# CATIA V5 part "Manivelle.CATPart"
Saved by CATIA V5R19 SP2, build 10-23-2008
Part number: Manivelle
Bounding box of the stored display mesh (mm): x -60 to 131.111, y -14 to 14, z -40 to 14
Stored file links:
  D:\thinkmotion-MPB\Dropbox\CIAO82010_JCF\SAINT-AIME\0558-SaintAime\CAO2\CAO\Manivelle.CATPart
  D:\thinkmotion-MPB\Dropbox\CIAO82010_JCF\SAINT-AIME\0558-SaintAime\CAO2\CAO\Mecanisme_558.CATProduct
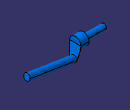
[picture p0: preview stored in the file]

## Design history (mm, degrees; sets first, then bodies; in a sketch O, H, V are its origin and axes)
Set1
  Plane1: type Offset, RefPlane xy-plane, Offset 20, reversed
  Plane2: type Offset, RefPlane Plane1, Offset 20, reversed
  Curve1: Elements (vertex [element of Sketch4 | element of Sketch4]; vertex [element of Sketch3 | element of Sketch3]; vertex [element of Sketch2 | element of Sketch2])
  Curve2: Elements (vertex [element of Sketch4 | element of Sketch4]; vertex [element of Sketch3 | element of Sketch3]; vertex [element of Sketch2 | element of Sketch2])
  Curve3: Elements (vertex [element of Sketch4 | element of Sketch4]; vertex [element of Sketch3 | element of Sketch3]; vertex [element of Sketch2 | element of Sketch2])
  Curve4: Elements (vertex [element of Sketch4 | element of Sketch4]; vertex [element of Sketch3 | element of Sketch3]; vertex [element of Sketch2 | element of Sketch2])
  Plane3: type Tangent, Support face of Pad1, RefPoint Sketch8.P1
  Point1: type OnSurface, Support end face of Pad3, Length 0, Direction (-0.6218, -0.213, 0.7536)
  Line1: type Normal, RefPoint Point1, RefSkin end face of Pad3, Start 0, End 20
  Line2: type Normal, RefPoint Sketch8.O, RefSkin xy-plane, Start 0, End 20
  Intersect1: ToIntersect1 Line2, ToIntersect2 Line1
  Point2: type OnPlane, Support end face of Pad1, H 0, V 0, Direction (0, 1, 0)
  Line3: type PtPt, FirstPoint Point2, SecondPoint Sketch8.P1
  Intersect2: ToIntersect1 Line3, ToIntersect2 Line1
Set2
  Point3: (10, 0, 0)
  Point4: (14.7998, 0, -31.2692)
  Line4: type PtPt, FirstPoint {point type Coord, X 10, Y 0, Z 0}, SecondPoint {point type Coord, X 14.7998, Y 0, Z -31.2692}
Set3
  Line5: type PtPt, FirstPoint {point type Coord, X 0, Y 0, Z -33.657}, SecondPoint {point type Coord, X 0, Y 43, Z 74.575}
  Line6: type Normal, RefPoint {point type Center, Curve edge [face of Pad2 from Sketch6.A1 | end face of Pad2]}, RefSkin end face of Pad2, Start 0, End 20
  Line7: type Normal, RefPoint {point type Center, Curve edge [end face of Pad3 | face of Pad3]}, RefSkin end face of Pad3, Start 0, End 20
  Intersect3: ToIntersect1 Line6, ToIntersect2 Line7
Body1 (main body)
  Sketch1 on yz-plane, origin (0, 0, 0), H (0, 1, 0), V (0, 0, 1)
    circle A1 centre (0, 0) radius 14
    radius A1 = 14
  Pad1: profile Sketch1, direction (1, 0, 0), length 10, mirrored extent
  Sketch2 on Plane2, origin (0, 0, -40), H (1, 0, 0), V (0, 1, 0)
    line L1 (16.14, 5) -> (16.14, -5)
    line L2 (16.14, -5) -> (12.0561, -3.8503)
    line L3 (16.14, 5) -> (12.0561, 3.8503)
    point P4 (12.0561, 3.8503)
    arc A1 centre (13.14, 0) radius 4 from (12.0561, 3.8503) to (12.0561, -3.8503) ccw
    point P5 (13.14, 0)
    point P6 (12.0561, 3.8503)
    reference projected line E1 (10, 14) -> (10, -14) from edge [face of Pad1 from Sketch1.A1 | end face of Pad1]
    length L1 = 10
    radius A1 = 4
    distance P5 L1 = 3
    distance L1 E1 = 6.14
    vertical: L1 V
    tangency: A1 L3, A1 L2
    coincidence: P6 P4
    symmetry: L3 L2 H
  Sketch3 on Plane1, origin (0, 0, -20), H (1, 0, 0), V (0, 1, 0)
    line L1 (13, 11) -> (13, -11)
    line L2 (13, -11) -> (5.9776, -6.9152)
    point P3 (5.9776, -6.9152)
    line L3 (13, 11) -> (5.9776, 6.9152)
    arc A1 centre (10, 0) radius 8 from (5.9776, 6.9152) to (5.9776, -6.9152) ccw
    point P5 (10, 0)
    point P6 (5.9776, -6.9152)
    reference projected line E1 (10, 14) -> (10, -14) from edge [face of Pad1 from Sketch1.A1 | end face of Pad1]
    distance L1 P5 = 3
    length L1 = 22
    radius A1 = 8
    distance L1 E1 = 3
    vertical: L1 V
    tangency: A1 L2, A1 L3
    symmetry: L3 L2 H
    coincidence: P6 P3
  Sketch4 on xy-plane, origin (0, 0, 0), H (1, 0, 0), V (0, 1, 0)
    line L1 (10, -13.8564) -> (1, -8.6603)
    line L2 (10, 13.8564) -> (1, 8.6603)
    arc A1 centre (6, 0) radius 10 from (1, -8.6603) to (1, 8.6603) cw
    point P5 (6, 0)
    line L3 (10, 13.8564) -> (10, -13.8564)
    reference projected line E1 (10, 14) -> (10, -14) from edge [face of Pad1 from Sketch1.A1 | end face of Pad1]
    radius A1 = 10
    distance L3 P5 = 4
    angle L1 L3 = 60
    tangency: A1 L1, L2 A1
    symmetry: L2 L1 H
    vertical: L3 V
    coincidence: L3 E1
  Loft1: solid, Sections (Sketch4; Sketch3; Sketch2)
  Sketch5 on Plane3, origin (9.6794, 0, 0.0423), H (0, -1, 0), V (-0.1593, 0, 0.9872)
    point P1 (7.3201, -34.173)
    line L1 (7.3201, -34.173) -> (12.5, -34.173)
    line L2 (12.5, -34.173) -> (12.5, -43.4625)
    line L3 (12.5, -43.4625) -> (-12.5, -43.4625)
    line L4 (-12.5, -43.4625) -> (-12.5, -34.173)
    line L5 (-12.5, -34.173) -> (-7.3201, -34.173)
    point P6 (-7.3201, -34.173)
    reference projected curve E1 from edge [face of Pad1 | face of Loft1]
    reference projected curve E2 from edge [face of Loft1 | face of Pad1]
    reference projected point E3 (0, -39.4451) from Sketch8.P2
    construction line L6 (-21.3899, -34.173) -> (19.4468, -34.173)
    arc A1 centre (0, -31.7273) radius 7.7179 from (-7.3201, -34.173) to (7.3201, -34.173) ccw
    point P16 (0, -39.4451)
    distance L4 L2 = 25
    distance H L3 = 43.4625
    horizontal: L1 H, L3 H, L5 H, L6 H
    vertical: L2 V, L4 V
    symmetry: L2 L4 V
    coincidence: P6 E1, P1 E2, L6 L5, L1 L6, A1 P16, P16 V, A1 E3
    tangency: A1 E1, A1 E2
  Pocket1: profile Sketch5, direction (0.9872, 0, 0.1593), length 10, mirrored extent
  Sketch6 on start face of Pad1, origin (-10, 0, 0), H (0, -1, 0), V (0, 0, 1)
    circle A1 centre (0, 0) radius 7
    radius A1 = 7
  Pad2: profile Sketch6, direction (-1, 0, 0), length 50
  Sketch7 on Plane3, origin (9.5327, 0, 0.9516), H (0, -1, 0), V (-0.1593, 0, 0.9872)
    circle A1 centre (0, -32.6484) radius 7.7179
    point P1 (0, -32.6484)
    reference projected arc E1 centre (0, -32.6484) radius 7.7179 from (-7.3042, -35.1411) to (7.3042, -35.1411) ccw from edge [face of Pocket1 from Sketch5.A1 | face of Loft1]
    reference projected arc E2 centre (0, -32.6484) radius 7.7179 from (-7.3042, -35.1411) to (7.3042, -35.1411) ccw from edge [face of Pocket1 from Sketch5.A1 | face of Loft1]
    coincidence: P1 V, A1 E2
    concentricity: A1 E1
  Pad3: profile Sketch7, direction (0.9872, 0, 0.1593), length 116.639
  Sketch8 on zx-plane, origin (0, 0, 0), H (-1, 0, 0), V (0, 0, 1)
    projected line E1 (-16.14, -40) -> (-9.14, -40) from face of Loft1
    point P1 (-16.14, -40)
    point P2 (-9.14, -40)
